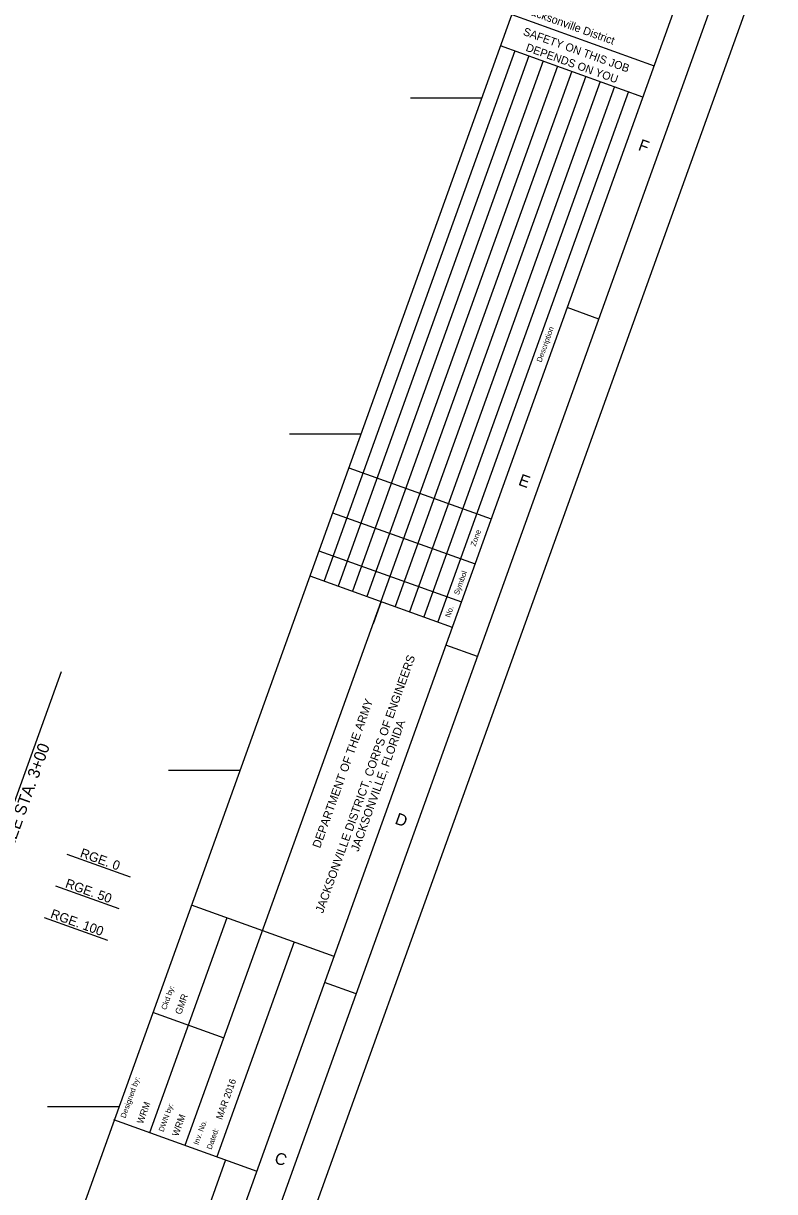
# Model space of a CAD drawing. Extents: x 609104 to 614395, y 782051 to 786739.
# Drawn here: x 613278 to 614395, y 783373 to 785111 of the extents above; entities that cross this region are included whole.
import ezdxf

# ---------------------------------------------------------------- set-up
doc = ezdxf.new("R2010")
doc.units = 0
for name, color, linetype in [('G-ANNO-NPLT', 7, 'Continuous'), ('G-ANNO-TEXT-DRWG', 7, 'Continuous'), ('G-ANNO-TEXT-PROJ', 7, 'Continuous'), ('G-ANNO-TEXT-TTLB', 7, 'Continuous'), ('G-ANNO-TTLB', 7, 'Continuous'), ('V-ALGN-TEXT', 7, 'Continuous'), ('V-ANNO-MATC', 7, 'Continuous'), ('V-ANNO-MATC-IDEN', 7, 'Continuous'), ('V-TOPO-COOR-STAT', 7, 'Continuous')]:
    doc.layers.add(name, color=color, linetype=linetype)

msp = doc.modelspace()

# ---------------------------------------------------------------- linework, layer by layer
at = {"layer": 'G-ANNO-NPLT'}
msp.add_lwpolyline([(610254.1, 786738.7), (614394.6, 785250.1), (613244.3, 782050.6), (609103.8, 783539.2)], close=True, dxfattribs=at)
at = {"layer": 'G-ANNO-TTLB'}
for p, q in [((614054.9, 785266), (612972.3, 782254.7)), ((614003.8, 785123.6), (614215.5, 785047.5)), ((613986.6, 785077.6), (614198.3, 785001.5)), ((614008.2, 785069.9), (613724.7, 784281.4)), ((614029.4, 785062.2), (613745.9, 784273.7)), ((614050.5, 785054.6), (613767, 784266.1)), ((614071.7, 785047), (613788.2, 784258.5)), ((614092.9, 785039.4), (613809.4, 784250.9)), ((614114, 785031.8), (613830.6, 784243.3)), ((614135.2, 785024.2), (613851.7, 784235.7)), ((614156.4, 785016.6), (613872.9, 784228.1)), ((614177.6, 785009), (613894.1, 784220.5)), ((614133.3, 784670.9), (614086.2, 784687.8)), ((613761.6, 784449.8), (613973.3, 784373.7)), ((613737.5, 784382.9), (613949.2, 784306.7)), ((613717.2, 784326.4), (613928.9, 784250.2)), ((613703.7, 784288.9), (613915.4, 784212.8)), ((613518.1, 783442.2), (613809.6, 784250.8)), ((613809.6, 784250.8), (613797.6, 784217.5)), ((613952.8, 784169), (613905.8, 784185.9)), ((613527.1, 783799.9), (613739.5, 783723.5)), ((613465.5, 783461.2), (613580.6, 783780.7)), ((613680.3, 783744.8), (613565.4, 783425.2)), ((613772.4, 783667.2), (613725.4, 783684.1)), ((613469.6, 783640.1), (613575.7, 783602)), ((613411.7, 783480.4), (613624.6, 783403.9)), ((613578.2, 783420.6), (613459.3, 783089.9))]:
    msp.add_line(p, q, dxfattribs=at)
for points in [[(609167.8, 783569.4), (613214.2, 782114.6), (614330.7, 785220), (610284.3, 786674.7)], [(614266.7, 785189.8), (610385, 786585.4), (609302.3, 783574.1), (613184.1, 782178.5)]]:
    msp.add_lwpolyline(points, close=True, dxfattribs=at)
at = {"layer": 'V-ALGN-TEXT'}
for p, q in [((613342.4, 783875), (613436.5, 783841.2)), ((613325.5, 783827.9), (613419.6, 783794.1)), ((613308.6, 783780.9), (613402.7, 783747.1))]:
    msp.add_line(p, q, dxfattribs=at)
at = {"layer": 'V-ANNO-MATC'}
msp.add_line((613333.7, 784146.4), (613129, 783577.2), dxfattribs=at)
at = {"layer": 'V-TOPO-COOR-STAT'}
for p, q in [((613853.1, 785000), (613959.3, 785000)), ((613673.3, 784500), (613779.6, 784500)), ((613493.5, 784000), (613599.8, 784000)), ((613313.8, 783500), (613420, 783500))]:
    msp.add_line(p, q, dxfattribs=at)

# ---------------------------------------------------------------- texts
at = {"layer": 'G-ANNO-TEXT-DRWG'}
for s, p in [('GMR', (613512.2, 783635.8)), ('WRM', (613455.4, 783473.3)), ('WRM', (613507.8, 783454.7))]:
    msp.add_text(s, height=10, rotation=70.2251, dxfattribs=at).set_placement(p)
at = {"layer": 'G-ANNO-TEXT-PROJ'}
msp.add_text('MAR 2016', height=10, rotation=70.2251, dxfattribs=at).set_placement((613572.9, 783479.5))
at = {"layer": 'G-ANNO-TEXT-TTLB'}
for s, height, rotation, p in [('Jacksonville District', 11.9, 340.2251, (614023.6, 785125.6)), ('SAFETY ON THIS JOB', 11.9, 340.2251, (614019.7, 785093.6)), ('DEPENDS ON YOU', 11.9, 340.2251, (614023.7, 785070)), ('Description', 8, 70.2251, (614047.9, 784605.9)), ('Zone', 8, 70.2251, (613949.8, 784332.2)), ('Symbol', 8, 70.2251, (613925.1, 784260)), ('No.', 8, 70.2251, (613911.9, 784226.4)), ('JACKSONVILLE DISTRICT, CORPS OF ENGINEERS', 12.5, 70.2251, (613723.2, 783786.5)), ('DEPARTMENT OF THE ARMY', 12.5, 70.2251, (613718.7, 783883.1)), ('JACKSONVILLE, FLORIDA', 12.5, 70.2251, (613775.8, 783877.9)), ('Ckd by:', 8, 70.2251, (613489.8, 783642.9)), ('Designed by:', 8, 70.2251, (613429.3, 783481.9)), ('DWN by:', 8, 70.2251, (613486, 783461.5)), ('Inv. No.', 8, 70.2251, (613537.7, 783442.1)), ('Dated:', 8, 70.2251, (613557.3, 783435.2))]:
    msp.add_text(s, height=height, rotation=rotation, dxfattribs=at).set_placement(p)
at = {"layer": 'G-ANNO-TTLB'}
for s, p in [('F', (614190.6, 784922.5)), ('E', (614012.4, 784424.6)), ('D', (613828.9, 783920.8)), ('C', (613649.6, 783416.5))]:
    msp.add_text(s, height=17.5, rotation=340.2251, dxfattribs=at).set_placement(p)
at = {"layer": 'V-ALGN-TEXT'}
for s, p in [('RGE. 0', (613360.9, 783871.3)), ('RGE. 50', (613338.9, 783826.1)), ('RGE. 100', (613316.9, 783780.9))]:
    msp.add_text(s, height=13.92, rotation=340.2251, dxfattribs=at).set_placement(p)
at = {"layer": 'V-ANNO-MATC-IDEN'}
msp.add_text('MATCHLINE SHEET NO. 013 LEE STA. 3+00', height=17.52, rotation=70.2251, dxfattribs=at).set_placement((613154.1, 783582.1))

doc.saveas('drawing.dxf')
